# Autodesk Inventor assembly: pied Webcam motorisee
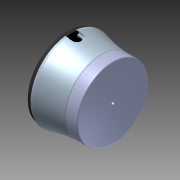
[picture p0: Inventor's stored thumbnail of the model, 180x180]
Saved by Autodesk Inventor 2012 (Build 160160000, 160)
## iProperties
Created: 2013-08
Part Number: pied Webcam motorisee
Document SubType Name: Assembly
Designer: hilarion
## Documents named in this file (4)
- D:\dominique\travail\année 2013-2014\TSTI2D\ITEC\Révision inventor\webcam motorisé\Composants importés\Webcam motorisee\pied Webcam motorisee.iam
- D:\dominique\travail\année 2013-2014\TSTI2D\ITEC\Révision inventor\webcam motorisé\Composants importés\Webcam motorisee\SE-Base.iam
- D:\dominique\travail\année 2013-2014\TSTI2D\ITEC\Révision inventor\webcam motorisé\Composants importés\Webcam motorisee\sortie_moteur.iam
- D:\dominique\travail\année 2013-2014\TSTI2D\ITEC\Révision inventor\webcam motorisé\Composants importés\Webcam motorisee\Pignon_étagé.iam
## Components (3 placed, 3 different names)
1. SE-Base:1 [sub-assembly]
2. sortie_moteur:1 [sub-assembly]
3. Pignon_étagé:1 [sub-assembly]
